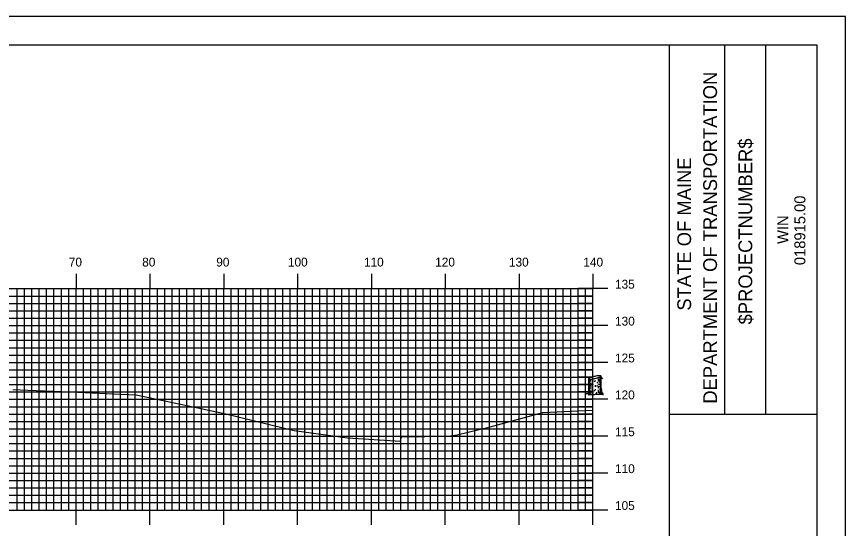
# Model space of a CAD drawing. Extents: x 854287 to 854631, y 366605 to 366825.
# Drawn here: x 854515 to 854627.3, y 366755.6 to 366824.9 of the extents above; entities that cross this region are included whole.
import ezdxf

# ---------------------------------------------------------------- set-up
doc = ezdxf.new("R2010")
doc.units = 0
for name, color, linetype in [('BORDER', 7, 'Continuous'), ('H_V ANNOTATION', 7, 'Continuous'), ('M_Trees_Conifer_Pay', 7, 'Continuous'), ('MAJOR', 7, 'Continuous'), ('MINOR', 7, 'Continuous'), ('PLOT BOUNDARY', 7, 'Continuous'), ('S_Roadway_Centerline', 7, 'Continuous')]:
    doc.layers.add(name, color=color, linetype=linetype)

msp = doc.modelspace()

# ---------------------------------------------------------------- linework, layer by layer
at = {"layer": 'BORDER'}
for p, q in [((854603.44, 366611.06), (854603.44, 366821.06)), ((854610.9, 366771.05), (854610.9, 366821.05)), ((854616.49, 366771.05), (854616.49, 366821.05)), ((854603.45, 366771.04), (854623.44, 366771.04))]:
    msp.add_line(p, q, dxfattribs=at)
msp.add_lwpolyline([(854303.44, 366611.06), (854623.44, 366611.06), (854623.44, 366821.06), (854303.44, 366821.06)], close=True, dxfattribs=at)
at = {"layer": 'M_Trees_Conifer_Pay'}
for p, q in [((854592.49, 366774.15), (854592.49, 366775.87)), ((854592.54, 366775.83), (854592.54, 366775.36)), ((854592.54, 366775.3), (854592.54, 366774.99)), ((854592.6, 366775.82), (854592.6, 366775.72)), ((854592.6, 366775.65), (854592.6, 366775.44)), ((854592.6, 366775.39), (854592.6, 366775.19)), ((854592.72, 366775.81), (854592.72, 366775.58)), ((854592.72, 366775.54), (854592.72, 366775.46)), ((854592.94, 366775.83), (854592.94, 366775.66)), ((854592.94, 366775.43), (854592.94, 366775.19)), ((854593.35, 366775.6), (854593.35, 366775.51)), ((854593.74, 366775.87), (854593.74, 366775.67)), ((854593.74, 366775.62), (854593.74, 366775.53)), ((854593.97, 366776.07), (854593.97, 366775.85)), ((854593.97, 366775.76), (854593.97, 366775.71)), ((854594.02, 366775.58), (854593.97, 366775.52)), ((854593.97, 366775.38), (854593.97, 366775.24)), ((854594.08, 366776.13), (854594.08, 366775.97)), ((854594.08, 366775.9), (854594.08, 366775.77)), ((854594.08, 366775.59), (854594.08, 366775.25)), ((854594.15, 366774.56), (854594.15, 366776.2)), ((854592.54, 366774.94), (854592.54, 366774.45)), ((854592.54, 366774.39), (854592.54, 366774.15)), ((854592.6, 366775.14), (854592.6, 366774.8)), ((854592.6, 366774.75), (854592.6, 366774.61)), ((854592.6, 366774.52), (854592.6, 366774.14)), ((854592.72, 366775.06), (854592.72, 366774.92)), ((854592.72, 366774.65), (854592.72, 366774.51)), ((854592.72, 366774.25), (854592.72, 366774.15)), ((854592.94, 366774.95), (854592.94, 366774.79)), ((854592.94, 366774.75), (854592.94, 366774.58)), ((854592.94, 366774.3), (854592.94, 366774.15)), ((854593.35, 366774.99), (854593.35, 366774.91)), ((854593.35, 366774.89), (854593.35, 366774.74)), ((854593.35, 366774.45), (854593.35, 366774.3)), ((854593.74, 366775.18), (854593.74, 366775.08)), ((854593.74, 366774.71), (854593.74, 366774.56)), ((854593.74, 366774.33), (854593.74, 366774.24)), ((854593.97, 366775.13), (854593.97, 366775.02)), ((854593.97, 366774.89), (854593.97, 366774.75)), ((854593.97, 366774.52), (854593.97, 366774.35)), ((854594.08, 366775.21), (854594.08, 366775.05)), ((854594.08, 366775), (854594.08, 366774.79)), ((854594.08, 366774.76), (854594.08, 366774.68)), ((854594.08, 366774.64), (854594.08, 366774.47)), ((854592.72, 366773.75), (854592.88, 366773.82)), ((854593.16, 366773.69), (854593.03, 366773.75))]:
    msp.add_line(p, q, dxfattribs=at)
for points in [[(854592.67, 366775.17), (854592.66, 366775.27), (854592.71, 366775.25), (854592.71, 366775.15)], [(854593.94, 366775.66), (854593.91, 366775.58), (854593.9, 366775.51), (854593.93, 366775.45)], [(854593.97, 366775.7), (854594.01, 366775.63), (854594.06, 366775.68), (854594.11, 366775.75), (854594.21, 366775.95), (854594.27, 366775.99), (854594.3, 366776)], [(854593.99, 366775.45), (854594.02, 366775.58), (854594.09, 366775.69), (854594.12, 366775.76), (854594.19, 366775.91)], [(854594.2, 366775.93), (854594.28, 366775.94), (854594.35, 366775.84)], [(854594.15, 366774.56), (854594.21, 366774.3), (854594.22, 366774.02), (854594.28, 366773.9), (854594.42, 366773.87), (854594.19, 366773.83), (854594.19, 366773.83), (854594.19, 366773.78), (854594.44, 366773.69), (854594.16, 366773.7), (854593.81, 366773.72), (854593.49, 366773.71), (854593.49, 366773.8), (854593.35, 366773.71), (854593.16, 366773.69), (854593.18, 366773.62), (854592.92, 366773.67), (854592.69, 366773.64), (854592.4, 366773.66), (854592.69, 366773.71), (854592.72, 366773.75), (854592.56, 366773.81), (854592.32, 366773.82), (854592.08, 366773.82), (854592.42, 366773.88), (854592.46, 366773.96), (854592.49, 366774.15)], [(854593.74, 366774.16), (854593.75, 366774.04), (854593.83, 366773.99)], [(854593.81, 366774.78), (854593.82, 366774.7), (854593.87, 366774.71), (854593.86, 366774.88)], [(854593.98, 366774.27), (854594.06, 366774.16), (854594.06, 366773.99), (854594.19, 366773.83)], [(854594.08, 366774.41), (854594.09, 366774.27), (854594.13, 366774.2), (854594.14, 366774)], [(854592.54, 366774.1), (854592.52, 366774.02), (854592.5, 366773.93)], [(854592.62, 366774.08), (854592.62, 366773.96), (854592.57, 366773.88), (854592.56, 366773.81)], [(854592.78, 366774.11), (854592.78, 366773.97), (854592.69, 366773.88)], [(854593.01, 366773.87), (854593.07, 366773.96), (854593.1, 366774.1)], [(854593.49, 366773.8), (854593.57, 366773.94), (854593.58, 366774.04)], [(854594.02, 366773.77), (854594.01, 366773.91), (854593.93, 366774.04)]]:
    msp.add_lwpolyline(points, dxfattribs=at)
for centre, radius, start, end in [((854592.54, 366775.86), 0.0527, 146.7194, 156.5158), ((854592.52, 366775.87), 0.0314, 156.5158, 169.2194), ((854592.52, 366775.87), 0.0264, 169.2194, 180.0315), ((854592.51, 366775.87), 0.0226, 180.0315, 191.7194), ((854592.51, 366775.87), 0.0226, 191.7194, 203.4074), ((854592.52, 366775.87), 0.0264, 203.4074, 214.2194), ((854592.52, 366775.87), 0.0314, 214.2194, 226.923), ((854592.52, 366775.69), 0.0334, 163.9485, 180), ((854592.52, 366775.69), 0.0334, 180, 196.0515), ((854592.53, 366775.69), 0.0441, 196.0515, 210), ((854592.55, 366775.7), 0.0624, 210, 228.7494), ((854592.52, 366775.24), 0.0334, 163.9485, 180), ((854592.57, 366775.84), 0.0817, 132.3887, 146.7194), ((854592.54, 366775.89), 0.0527, 226.923, 236.7194), ((854592.68, 366775.72), 0.251, 124.2194, 132.3887), ((854592.55, 366775.91), 0.0817, 236.7194, 251.0501), ((854592.62, 366775.78), 0.172, 228.7494, 240), ((854592.61, 366776.07), 0.251, 251.0501, 259.2194), ((854592.99, 366775.26), 0.802, 108.0594, 124.2194), ((854592.82, 366776.13), 0.571, 240, 240.3367), ((854592.82, 366775.92), 0.571, 240, 247.0587), ((854592.71, 366776.61), 0.802, 259.2194, 275.3794), ((854592.82, 366776.13), 0.571, 246.8597, 257.9846), ((854594.35, 366771.1), 5.18, 101.7194, 108.0594), ((854592.3, 366780.97), 5.18, 275.3794, 281.7194), ((854593.32, 366779.88), 4.12, 264.6955, 266.7331), ((854593.32, 366779.65), 4.12, 268.0751, 270), ((854594.35, 366771.1), 5.18, 95.3794, 101.7194), ((854593.32, 366779.65), 4.12, 270, 270.3581), ((854592.3, 366780.97), 5.18, 281.7194, 288.0594), ((854593.32, 366779.44), 4.12, 273.7052, 275.9504), ((854593.32, 366779.65), 4.12, 275.7849, 277.0558), ((854593.32, 366779.88), 4.12, 276.238, 278.1032), ((854593.94, 366775.46), 0.802, 79.2194, 95.3794), ((854593.66, 366776.81), 0.802, 288.0594, 304.2194), ((854593.82, 366776.36), 0.571, 278.1032, 284.3667), ((854593.82, 366776.52), 0.571, 284.4317, 292.4132), ((854593.82, 366775.92), 0.571, 284.4493, 297.0429), ((854593.82, 366776.36), 0.571, 297.0237, 300), ((854594.04, 366776), 0.251, 71.0501, 79.2194), ((854593.97, 366776.35), 0.251, 304.2194, 312.3887), ((854594.02, 366776.17), 0.172, 300, 311.2506), ((854594.02, 366776.02), 0.172, 300, 311.2506), ((854594.09, 366776.16), 0.0817, 56.7194, 71.0501), ((854594.08, 366776.23), 0.0817, 312.3887, 326.7194), ((854594.11, 366776.18), 0.0527, 46.923, 56.7194), ((854594.1, 366776.09), 0.0624, 311.2506, 330), ((854594.1, 366775.94), 0.0624, 311.2506, 330), ((854594.13, 366776.2), 0.0264, 23.4074, 34.2194), ((854594.12, 366776.2), 0.0314, 34.2194, 46.923), ((854594.13, 366776.2), 0.0226, 11.7194, 23.4074), ((854594.13, 366776.2), 0.0226, 0.0315, 11.7194), ((854594.12, 366776.2), 0.0314, 336.5158, 349.2194), ((854594.13, 366776.2), 0.0264, 349.2194, 0.0315), ((854594.1, 366776.21), 0.0527, 326.7194, 336.5158), ((854594.11, 366776.08), 0.0441, 330, 343.9485), ((854594.12, 366776.08), 0.0334, 343.9485, 354.2151), ((854594.12, 366775.92), 0.0334, 343.9485, 354.2151), ((854594.11, 366775.93), 0.0441, 330, 343.9485), ((854594.12, 366775.48), 0.0334, 343.9485, 354.2151), ((854592.52, 366775.24), 0.0334, 180, 196.0515), ((854592.53, 366775.25), 0.0441, 196.0515, 210), ((854592.55, 366775.26), 0.0624, 210, 228.7494), ((854592.52, 366775.03), 0.0334, 163.9485, 180), ((854592.52, 366775.03), 0.0334, 180, 196.0515), ((854592.53, 366775.04), 0.0441, 196.0515, 210), ((854592.55, 366775.05), 0.0624, 210, 228.7494), ((854592.52, 366774.8), 0.0334, 163.9485, 180), ((854592.52, 366774.8), 0.0334, 180, 196.0515), ((854592.53, 366774.8), 0.0441, 196.0515, 210), ((854592.55, 366774.81), 0.0624, 210, 228.7494), ((854592.52, 366774.6), 0.0334, 163.9485, 180), ((854592.52, 366774.4), 0.0334, 163.9485, 180), ((854592.52, 366774.4), 0.0334, 180, 196.0515), ((854592.53, 366774.41), 0.0441, 196.0515, 210), ((854592.55, 366774.42), 0.0624, 210, 228.7494), ((854592.52, 366774.18), 0.0334, 163.9485, 180), ((854592.52, 366774.18), 0.0334, 180, 196.0515), ((854592.53, 366774.19), 0.0441, 196.0515, 210), ((854592.55, 366774.2), 0.0624, 210, 228.7494), ((854592.62, 366775.34), 0.172, 228.7494, 240), ((854592.62, 366775.13), 0.172, 228.7494, 240), ((854592.62, 366774.89), 0.172, 228.7494, 240), ((854592.62, 366774.5), 0.172, 228.7494, 240), ((854592.62, 366774.28), 0.172, 228.7494, 240), ((854592.82, 366775.68), 0.571, 240, 240.3367), ((854592.82, 366775.47), 0.571, 240, 246.8597), ((854592.82, 366775.24), 0.571, 240, 246.8597), ((854592.81, 366775.04), 0.571, 241.2369, 248.0268), ((854592.82, 366774.84), 0.571, 240, 246.8597), ((854592.82, 366774.62), 0.571, 240, 244.5314), ((854592.82, 366775.47), 0.571, 259.2707, 261.8968), ((854593.32, 366778.99), 4.12, 261.8968, 263.1474), ((854593.32, 366778.56), 4.12, 263.4991, 265.8397), ((854593.32, 366779.2), 4.12, 264.081, 266.6676), ((854593.32, 366778.75), 4.12, 264.716, 266.3193), ((854593.32, 366778.36), 4.12, 267.8117, 270), ((854593.32, 366778.99), 4.12, 270, 270.3581), ((854593.32, 366778.36), 4.12, 270, 270.1328), ((854593.32, 366778.99), 4.12, 273.1493, 275.4569), ((854593.32, 366778.36), 4.12, 275.7849, 276.7896), ((854593.32, 366779.2), 4.12, 277.6125, 278.1032), ((854593.82, 366775.68), 0.571, 278.1032, 286.9296), ((854593.82, 366775.24), 0.571, 285.3983, 297.1896), ((854593.82, 366774.84), 0.571, 288.5067, 297.2721), ((854593.82, 366775.04), 0.571, 289.2907, 300), ((854593.82, 366775.68), 0.571, 297.1896, 300), ((854593.82, 366775.47), 0.571, 297.1896, 300), ((854594.02, 366775.34), 0.172, 300, 311.2506), ((854594.02, 366775.13), 0.172, 300, 311.2506), ((854594.02, 366774.69), 0.172, 300, 311.2506), ((854594.02, 366774.28), 0.172, 300, 311.2506), ((854594.09, 366775.26), 0.0624, 311.2506, 330), ((854594.09, 366775.05), 0.0624, 311.2506, 330), ((854594.09, 366774.61), 0.0624, 311.2506, 330), ((854594.09, 366774.2), 0.0624, 311.2506, 330), ((854594.12, 366775.24), 0.0334, 343.9485, 354.2151), ((854594.11, 366775.25), 0.0441, 330, 343.9485), ((854594.12, 366775.03), 0.0334, 343.9485, 354.2151), ((854594.11, 366775.04), 0.0441, 330, 343.9485), ((854594.12, 366774.6), 0.0334, 343.9485, 354.2151), ((854594.11, 366774.6), 0.0441, 330, 343.9485), ((854594.12, 366774.18), 0.0334, 343.9485, 354.2151), ((854594.11, 366774.19), 0.0441, 330, 343.9485), ((854593.32, 366778.14), 4.12, 262.4438, 263.512), ((854593.32, 366778.14), 4.12, 277.3684, 278.1032), ((854593.82, 366774.62), 0.571, 278.1032, 281.637)]:
    msp.add_arc(centre, radius, start, end, dxfattribs=at)
at = {"layer": 'MAJOR'}
for p, q in [((854523.04, 366790.06), (854523.04, 366788.06)), ((854533.04, 366790.06), (854533.04, 366788.06)), ((854543.04, 366790.06), (854543.04, 366788.06)), ((854553.04, 366790.06), (854553.04, 366788.06)), ((854563.04, 366790.06), (854563.04, 366788.06)), ((854573.04, 366790.06), (854573.04, 366788.06)), ((854583.04, 366790.06), (854583.04, 366788.06)), ((854593.04, 366790.06), (854593.04, 366788.06)), ((854313.04, 366788.06), (854593.04, 366788.06)), ((854313.04, 366788.06), (854593.04, 366788.06)), ((854523.04, 366758.06), (854523.04, 366788.06)), ((854533.04, 366758.06), (854533.04, 366788.06)), ((854543.04, 366758.06), (854543.04, 366788.06)), ((854553.04, 366758.06), (854553.04, 366788.06)), ((854563.04, 366758.06), (854563.04, 366788.06)), ((854573.04, 366758.06), (854573.04, 366788.06)), ((854583.04, 366758.06), (854583.04, 366788.06)), ((854595.05, 366788.06), (854591.04, 366788.06)), ((854593.04, 366758.06), (854593.04, 366788.06)), ((854593.04, 366758.06), (854593.04, 366788.06)), ((854313.04, 366783.06), (854593.04, 366783.06)), ((854595.05, 366783.06), (854591.04, 366783.06)), ((854313.04, 366778.06), (854593.04, 366778.06)), ((854595.05, 366778.06), (854591.04, 366778.06)), ((854313.04, 366773.06), (854593.04, 366773.06)), ((854595.05, 366773.06), (854591.04, 366773.06)), ((854313.04, 366768.06), (854593.04, 366768.06)), ((854595.05, 366768.06), (854591.04, 366768.06)), ((854313.04, 366763.06), (854593.04, 366763.06)), ((854595.05, 366763.06), (854591.04, 366763.06)), ((854313.04, 366758.06), (854593.04, 366758.06)), ((854313.04, 366758.06), (854593.04, 366758.06)), ((854523.04, 366756.05), (854523.04, 366758.06)), ((854533.04, 366756.05), (854533.04, 366758.06)), ((854543.04, 366756.05), (854543.04, 366758.06)), ((854553.04, 366756.05), (854553.04, 366758.06)), ((854563.04, 366756.05), (854563.04, 366758.06)), ((854573.04, 366756.05), (854573.04, 366758.06)), ((854583.04, 366756.05), (854583.04, 366758.06)), ((854595.05, 366758.06), (854591.04, 366758.06)), ((854593.04, 366756.05), (854593.04, 366758.06))]:
    msp.add_line(p, q, dxfattribs=at)
at = {"layer": 'MINOR'}
for p, q in [((854515.04, 366758.06), (854515.04, 366788.06)), ((854516.04, 366758.06), (854516.04, 366788.06)), ((854517.04, 366758.06), (854517.04, 366788.06)), ((854518.04, 366758.06), (854518.04, 366788.06)), ((854519.04, 366758.06), (854519.04, 366788.06)), ((854520.04, 366758.06), (854520.04, 366788.06)), ((854521.04, 366758.06), (854521.04, 366788.06)), ((854522.04, 366758.06), (854522.04, 366788.06)), ((854524.04, 366758.06), (854524.04, 366788.06)), ((854525.04, 366758.06), (854525.04, 366788.06)), ((854526.04, 366758.06), (854526.04, 366788.06)), ((854527.04, 366758.06), (854527.04, 366788.06)), ((854528.04, 366758.06), (854528.04, 366788.06)), ((854529.04, 366758.06), (854529.04, 366788.06)), ((854530.04, 366758.06), (854530.04, 366788.06)), ((854531.04, 366758.06), (854531.04, 366788.06)), ((854532.04, 366758.06), (854532.04, 366788.06)), ((854534.04, 366758.06), (854534.04, 366788.06)), ((854535.04, 366758.06), (854535.04, 366788.06)), ((854536.04, 366758.06), (854536.04, 366788.06)), ((854537.04, 366758.06), (854537.04, 366788.06)), ((854538.04, 366758.06), (854538.04, 366788.06)), ((854539.04, 366758.06), (854539.04, 366788.06)), ((854540.04, 366758.06), (854540.04, 366788.06)), ((854541.04, 366758.06), (854541.04, 366788.06)), ((854542.04, 366758.06), (854542.04, 366788.06)), ((854544.04, 366758.06), (854544.04, 366788.06)), ((854545.04, 366758.06), (854545.04, 366788.06)), ((854546.04, 366758.06), (854546.04, 366788.06)), ((854547.04, 366758.06), (854547.04, 366788.06)), ((854548.04, 366758.06), (854548.04, 366788.06)), ((854549.04, 366758.06), (854549.04, 366788.06)), ((854550.04, 366758.06), (854550.04, 366788.06)), ((854551.04, 366758.06), (854551.04, 366788.06)), ((854552.04, 366758.06), (854552.04, 366788.06)), ((854554.04, 366758.06), (854554.04, 366788.06)), ((854555.04, 366758.06), (854555.04, 366788.06)), ((854556.04, 366758.06), (854556.04, 366788.06)), ((854557.04, 366758.06), (854557.04, 366788.06)), ((854558.04, 366758.06), (854558.04, 366788.06)), ((854559.04, 366758.06), (854559.04, 366788.06)), ((854560.04, 366758.06), (854560.04, 366788.06)), ((854561.04, 366758.06), (854561.04, 366788.06)), ((854562.04, 366758.06), (854562.04, 366788.06)), ((854564.04, 366758.06), (854564.04, 366788.06)), ((854565.04, 366758.06), (854565.04, 366788.06)), ((854566.04, 366758.06), (854566.04, 366788.06)), ((854567.04, 366758.06), (854567.04, 366788.06)), ((854568.04, 366758.06), (854568.04, 366788.06)), ((854569.04, 366758.06), (854569.04, 366788.06)), ((854570.04, 366758.06), (854570.04, 366788.06)), ((854571.04, 366758.06), (854571.04, 366788.06)), ((854572.04, 366758.06), (854572.04, 366788.06)), ((854574.04, 366758.06), (854574.04, 366788.06)), ((854575.04, 366758.06), (854575.04, 366788.06)), ((854576.04, 366758.06), (854576.04, 366788.06)), ((854577.04, 366758.06), (854577.04, 366788.06)), ((854578.04, 366758.06), (854578.04, 366788.06)), ((854579.04, 366758.06), (854579.04, 366788.06)), ((854580.04, 366758.06), (854580.04, 366788.06)), ((854581.04, 366758.06), (854581.04, 366788.06)), ((854582.04, 366758.06), (854582.04, 366788.06)), ((854584.04, 366758.06), (854584.04, 366788.06)), ((854585.04, 366758.06), (854585.04, 366788.06)), ((854586.04, 366758.06), (854586.04, 366788.06)), ((854587.04, 366758.06), (854587.04, 366788.06)), ((854588.04, 366758.06), (854588.04, 366788.06)), ((854589.04, 366758.06), (854589.04, 366788.06)), ((854590.04, 366758.06), (854590.04, 366788.06)), ((854591.04, 366758.06), (854591.04, 366788.06)), ((854592.04, 366758.06), (854592.04, 366788.06)), ((854313.04, 366787.06), (854593.04, 366787.06)), ((854593.04, 366787.06), (854591.04, 366787.06)), ((854313.04, 366786.06), (854593.04, 366786.06)), ((854593.04, 366786.06), (854591.04, 366786.06)), ((854313.04, 366785.06), (854593.04, 366785.06)), ((854593.04, 366785.06), (854591.04, 366785.06)), ((854313.04, 366784.06), (854593.04, 366784.06)), ((854593.04, 366784.06), (854591.04, 366784.06)), ((854313.04, 366782.06), (854593.04, 366782.06)), ((854593.04, 366782.06), (854591.04, 366782.06)), ((854313.04, 366781.06), (854593.04, 366781.06)), ((854593.04, 366781.06), (854591.04, 366781.06)), ((854313.04, 366780.06), (854593.04, 366780.06)), ((854593.04, 366780.06), (854591.04, 366780.06)), ((854313.04, 366779.06), (854593.04, 366779.06)), ((854593.04, 366779.06), (854591.04, 366779.06)), ((854313.04, 366777.06), (854593.04, 366777.06)), ((854593.04, 366777.06), (854591.04, 366777.06)), ((854313.04, 366776.06), (854593.04, 366776.06)), ((854593.04, 366776.06), (854591.04, 366776.06)), ((854313.04, 366775.06), (854593.04, 366775.06)), ((854593.04, 366775.06), (854591.04, 366775.06)), ((854313.04, 366774.06), (854593.04, 366774.06)), ((854593.04, 366774.06), (854591.04, 366774.06)), ((854313.04, 366772.06), (854593.04, 366772.06)), ((854593.04, 366772.06), (854591.04, 366772.06)), ((854313.04, 366771.06), (854593.04, 366771.06)), ((854593.04, 366771.06), (854591.04, 366771.06)), ((854313.04, 366770.06), (854593.04, 366770.06)), ((854593.04, 366770.06), (854591.04, 366770.06)), ((854313.04, 366769.06), (854593.04, 366769.06)), ((854593.04, 366769.06), (854591.04, 366769.06)), ((854313.04, 366767.06), (854593.04, 366767.06)), ((854593.04, 366767.06), (854591.04, 366767.06)), ((854313.04, 366766.06), (854593.04, 366766.06)), ((854593.04, 366766.06), (854591.04, 366766.06)), ((854313.04, 366765.06), (854593.04, 366765.06)), ((854313.04, 366764.06), (854593.04, 366764.06)), ((854593.04, 366765.06), (854591.04, 366765.06)), ((854593.04, 366764.06), (854591.04, 366764.06)), ((854313.04, 366762.06), (854593.04, 366762.06)), ((854593.04, 366762.06), (854591.04, 366762.06)), ((854313.04, 366761.06), (854593.04, 366761.06)), ((854593.04, 366761.06), (854591.04, 366761.06)), ((854313.04, 366760.06), (854593.04, 366760.06)), ((854593.04, 366760.06), (854591.04, 366760.06)), ((854313.04, 366759.06), (854593.04, 366759.06)), ((854593.04, 366759.06), (854591.04, 366759.06))]:
    msp.add_line(p, q, dxfattribs=at)
at = {"layer": 'PLOT BOUNDARY'}
msp.add_lwpolyline([(854287.26, 366604.94), (854627.26, 366604.94), (854627.26, 366824.94), (854287.26, 366824.94)], close=True, dxfattribs=at)
at = {"layer": 'S_Roadway_Centerline'}
msp.add_lwpolyline([(854514.48, 366774.37), (854516.5, 366774.3), (854523.27, 366774.03), (854527.17, 366773.85), (854531.15, 366773.65), (854538.9, 366772.06), (854543.32, 366771.11), (854552.56, 366768.85), (854559.8, 366767.82), (854566.98, 366767.4), (854567.11, 366767.97), (854573.46, 366768.05), (854574.67, 366768.24), (854579.12, 366769.31), (854586.28, 366771.27), (854593.04, 366771.61)], dxfattribs=at)

# ---------------------------------------------------------------- texts
at = {"layer": 'BORDER'}
for s, height, p in [('DEPARTMENT OF TRANSPORTATION', 1.8635, (854609.86, 366772.47)), ('$PROJECTNUMBER$', 1.8635, (854614.63, 366783.21)), ('STATE OF MAINE', 1.8635, (854606.35, 366785.08)), ('018915.00', 1.491, (854621.83, 366791.25)), ('WIN', 1.491, (854619.52, 366794.12))]:
    msp.add_text(s, height=height, rotation=90, dxfattribs=at).set_placement(p)
at = {"layer": 'H_V ANNOTATION'}
for s, p in [('70', (854522.05, 366791.06)), ('80', (854531.99, 366791.06)), ('90', (854542.02, 366791.06)), ('100', (854551.73, 366791.06)), ('110', (854562.03, 366791.06)), ('120', (854571.68, 366791.06)), ('130', (854581.67, 366791.06)), ('140', (854591.75, 366791.06)), ('135', (854596.04, 366788.06)), ('130', (854596.04, 366783.06)), ('125', (854596.04, 366778.06)), ('120', (854596.04, 366773.06)), ('115', (854596.04, 366768.06)), ('110', (854596.04, 366763.06)), ('105', (854596.04, 366758.06))]:
    msp.add_text(s, height=1.2, dxfattribs=at).set_placement(p)

doc.saveas('drawing.dxf')
